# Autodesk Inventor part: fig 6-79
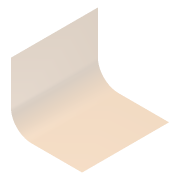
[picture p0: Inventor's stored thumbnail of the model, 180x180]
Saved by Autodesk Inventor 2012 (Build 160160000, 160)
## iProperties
Shininess: 64.0
Length Units: 11269
Angle Units: 11279
Time Units: 11290
Mass Units: 11283
Length Display Precision: 3
Angle Display Precision: 2
Compacted: True
Part Number: fig 6-79
Document SubType Name: Modeling
Created: 2003-10
Designer: Owner
Manufacturer: Standard
Standards Organization: Custom
Density: 1 g/cm^3
Material: Default
Density: 0.0
Volumn: 0.0
Area: 0.0
PropertySet Name: Model Information
Control State: 0
Master: False
Checked Out: False
Author: Owner
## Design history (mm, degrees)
node "Sketch1"
sketch "Sketch2"
  geometry: L1 (22.777, 31.862)-(22.777, 0.2); L2 (7.777, -14.8)-(-29.161, -14.8); A1 r 15 centre (7.777, 0.2) between (7.777, -14.8) and (22.777, 0.2)
  constraints: 4 end point, 2 point on circle, 2 tangent, 1 centre point, 1 perpendicular, 1 vertical
  dimensions: "d23" = 15 radius of A1
extrude_surface "ExtrusionSrf1" sketch "Sketch2" dims "d24" = 63.5, "d25" = 0
body "Srf1"
